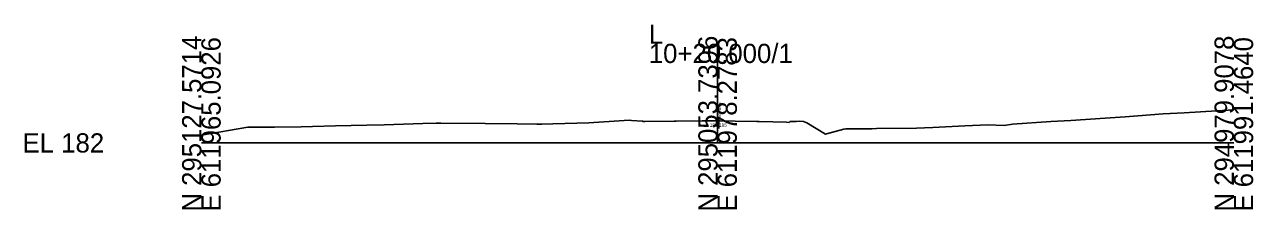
# Model space of a CAD drawing. Extents: x -81 to 616364, y 450 to 299952.
# Drawn here: x 535426.7 to 535605.2, y 115338.7 to 115365.6 of the extents above; entities that cross this region are included whole.
import ezdxf

# ---------------------------------------------------------------- set-up
doc = ezdxf.new("R2010")
doc.units = 0
for name, color, linetype in [('Exist XS Ground Line', 7, 'Continuous'), ('Old_Level_63', 7, 'Continuous'), ('Prop XS Side Slope Text', 7, 'Continuous')]:
    doc.layers.add(name, color=color, linetype=linetype)

msp = doc.modelspace()

# ---------------------------------------------------------------- linework, layer by layer
at = {"layer": 'Exist XS Ground Line'}
msp.add_lwpolyline([(535452.36, 115349.47), (535459.1, 115350.65), (535462.97, 115350.63), (535466.84, 115350.68), (535468.51, 115350.73), (535471.84, 115350.84), (535476.39, 115350.96), (535478.92, 115351.01), (535484.53, 115351.19), (535486.49, 115351.22), (535487.13, 115351.22), (535493.57, 115351.21), (535498.26, 115351.14), (535501.09, 115351.08), (535501.8, 115351.1), (535503.41, 115351.13), (535508.63, 115351.26), (535513.76, 115351.61), (535514.58, 115351.66), (535514.84, 115351.64), (535516.44, 115351.52), (535516.56, 115351.5), (535516.79, 115351.48), (535521.06, 115351.51), (535521.33, 115351.51), (535525.14, 115351.55), (535527.36, 115351.56), (535527.75, 115351.56), (535529.9, 115351.54), (535533.06, 115351.48), (535533.42, 115351.47), (535537.35, 115351.36), (535537.75, 115351.33), (535537.9, 115351.48), (535538.76, 115351.49), (535539.2, 115351.51), (535539.84, 115351.5), (535540.34, 115351.3), (535543.05, 115349.64), (535543.16, 115349.66), (535545.7, 115350.38), (535546.01, 115350.39), (535547.25, 115350.39), (535549.78, 115350.42), (535550.46, 115350.45), (535556.25, 115350.53), (535557.41, 115350.57), (535558.63, 115350.61), (535563.27, 115350.85), (535566.63, 115350.97), (535569, 115350.91), (535570.21, 115351.11), (535575.78, 115351.49), (535578.69, 115351.63), (535583.67, 115351.95), (535586.59, 115352.18), (535592.09, 115352.57), (535595.14, 115352.75), (535599.89, 115353.04), (535602.36, 115353.17)], dxfattribs=at)
at = {"layer": 'Old_Level_63'}
for p, q in [((535527.36, 115348.36), (535527.36, 115362.79)), ((535452.36, 115348.36), (535527.36, 115348.36)), ((535527.36, 115348.36), (535602.36, 115348.36))]:
    msp.add_line(p, q, dxfattribs=at)

# ---------------------------------------------------------------- texts
for s, p in [('L', (535517.36, 115362.79)), ('10+20.000/1', (535517.36, 115359.99)), ('EL 182', (535426.37, 115346.96))]:
    msp.add_text(s, height=2.8, dxfattribs=at).set_placement(p)
for s, p in [('N 295127.5714', (535452.36, 115338.36)), ('E 611965.0926', (535455.16, 115338.36)), ('N 295053.7396', (535527.36, 115338.36)), ('E 611978.2783', (535530.16, 115338.36)), ('N 294979.9078', (535602.36, 115338.37)), ('E 611991.4640', (535605.16, 115338.36))]:
    msp.add_text(s, height=2.8, rotation=90, dxfattribs=at).set_placement(p)
at = {"layer": 'Prop XS Side Slope Text'}
msp.add_text(' 185.195', height=0.5, rotation=90, dxfattribs=at).set_placement((535527.86, 115351.56))
msp.add_text('185.195', height=0.5, dxfattribs=at).set_placement((535526.22, 115350.7))

doc.saveas('drawing.dxf')
